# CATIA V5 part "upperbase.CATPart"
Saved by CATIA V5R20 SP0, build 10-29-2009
Part number: upperbase
Bounding box of the stored display mesh (mm): x 0 to 350, y 0 to 555, z -596 to 5
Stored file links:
  C:\Users\khanm\Downloads\Catia Project\Catia Project\upperbase.CATPart
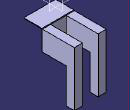
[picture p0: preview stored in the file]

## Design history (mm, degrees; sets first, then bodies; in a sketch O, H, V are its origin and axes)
Body1 (main body)
  Sketch1 on xy-plane, origin (0, 0, 0), H (1, 0, 0), V (0, 1, 0)
    line L1 (0, 0) -> (350, 0)
    line L2 (350, 0) -> (350, 200)
    line L3 (350, 200) -> (0, 200)
    line L4 (0, 200) -> (0, 0)
    length L1 = 350
    length L2 = 200
    horizontal: L1 H, L3 H
    vertical: L2 V, L4 V
  Pad1: profile Sketch1, direction (0, 0, 1), length 5
  Sketch2 on face of Pad1 from Sketch1.L3, origin (0, 200, 0), H (-1, 0, 0), V (0, 0, 1)
    line L1 (-350, 5) -> (0, 5)
    line L2 (0, 5) -> (0, -217)
    line L3 (0, -217) -> (-350, -217)
    line L4 (-350, -217) -> (-350, 5)
    reference projected line E1 (-350, 5) -> (0, 5) from edge [face of Pad1 from Sketch1.L3 | end face of Pad1]
    reference projected line E2 (-350, 0) -> (-350, 5) from edge [face of Pad1 from Sketch1.L3 | face of Pad1 from Sketch1.L2]
    reference projected line E3 (0, 0) -> (0, 5) from edge [face of Pad1 from Sketch1.L4 | face of Pad1 from Sketch1.L3]
    length L4 = 222
    horizontal: L1 H, L3 H
    vertical: L2 V, L4 V
    coincidence: L1 E1, E2 L4, E3 L2
  Pad2: profile Sketch2, direction (0, 1, 0), length 5
  Fillet1: radius 5, on edge [face of Pad2 | end face of Pad2]
  Sketch3 on end face of Pad2, origin (0, 205, 0), H (-1, 0, 0), V (0, 0, 1)
    line L1 (-350, 0) -> (-261, 0)
    line L2 (-261, 0) -> (-261, -217)
    line L3 (-261, -217) -> (-350, -217)
    line L4 (-350, -217) -> (-350, 0)
    reference projected line E1 (-350, -217) -> (0, -217) from edge [face of Pad2 from Sketch2.L3 | end face of Pad2]
    reference projected line E2 (-350, 5) -> (-350, -217) from edge [face of Pad2 | end face of Pad2]
    reference projected line E3 (0, 0) -> (-350, 0) from edge [face of Fillet1 | end face of Pad2]
    line L5 (-89, 0) -> (0, 0)
    line L6 (0, 0) -> (0, -217)
    line L7 (0, -217) -> (-89, -217)
    line L8 (-89, -217) -> (-89, 0)
    reference projected line E4 (0, -217) -> (0, 5) from edge [face of Pad2 | end face of Pad2]
    reference projected line E5 (-350, -217) -> (0, -217) from edge [face of Pad2 from Sketch2.L3 | end face of Pad2]
    reference projected line E6 (0, 0) -> (-350, 0) from edge [face of Fillet1 | end face of Pad2]
    distance L2 L4 = 89
    distance L6 L8 = 89
    horizontal: L1 H, L3 H, L5 H, L7 H
    vertical: L2 V, L4 V, L6 V, L8 V
    coincidence: L3 E1, L4 E2, L1 E3, L6 E4, E5 L7, L5 E6
  Pad3: profile Sketch3, direction (0, 1, 0), length 350
  Sketch4 on face of Pad3, origin (0, 0, -217), H (1, 0, 0), V (0, -1, 0)
    line L1 (0, -467.96) -> (89, -467.96)
    line L2 (89, -467.96) -> (89, -555)
    line L3 (89, -555) -> (0, -555)
    line L4 (0, -555) -> (0, -467.96)
    reference projected line E1 (0, -555) -> (89, -555) from edge [face of Pad3 | end face of Pad3]
    reference projected line E3 (89, -205) -> (89, -555) from edge [face of Pad3 | face of Pad3 from Sketch3.L8]
    reference projected line E4 (0, -200) -> (0, -205) from edge [face of Pad3 | face of Pad3]
    line L5 (261, -467.96) -> (350, -467.96)
    line L6 (350, -467.96) -> (350, -555)
    line L7 (350, -555) -> (261, -555)
    line L8 (261, -555) -> (261, -467.96)
    reference projected line E5 (350, -200) -> (350, -205) from edge [face of Pad3 | face of Pad3]
    reference projected line E6 (0, -555) -> (89, -555) from edge [face of Pad3 | end face of Pad3]
    reference projected line E8 (261, -205) -> (261, -555) from edge [face of Pad3 from Sketch3.L2 | face of Pad3]
    length L4 = 87.04
    length L6 = 87.04
    horizontal: L1 H, L3 H, L5 H, L7 H
    vertical: L2 V, L4 V, L6 V, L8 V
    coincidence: L3 E1, L2 E3, L4 E4, L6 E5, L7 E6, L8 E8
  Pad4: profile Sketch4, direction (0, 0, -1), length 379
